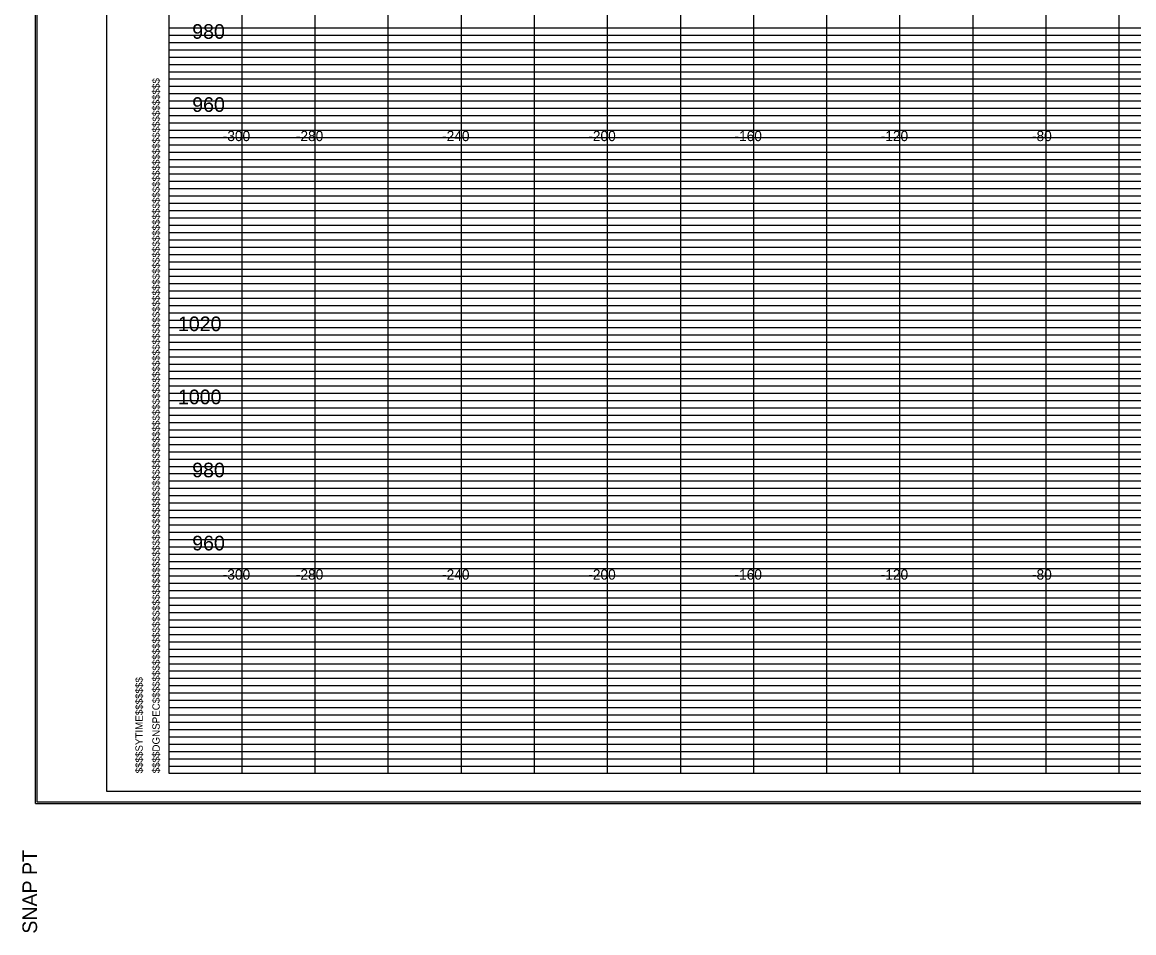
# Model space of a CAD drawing. Extents: x 2313580 to 2322968, y 282099 to 303247.
# Drawn here: x 2316841.2 to 2317145.2, y 287544 to 287793.2 of the extents above; entities that cross this region are included whole.
import ezdxf

# ---------------------------------------------------------------- set-up
doc = ezdxf.new("R2010")
doc.units = 0
for name, color, linetype in [('DESIGN - SHEET - Corner Text', 7, 'Continuous'), ('DESIGN - SHEET - Light Grid', 7, 'Continuous'), ('DESIGN - SHEET - Linework', 7, 'Continuous'), ('DESIGN - SHEET - Plot Shape', 7, 'Continuous'), ('DESIGN - TYPICAL - Text', 7, 'Continuous')]:
    doc.layers.add(name, color=color, linetype=linetype)

msp = doc.modelspace()

# ---------------------------------------------------------------- linework, layer by layer
at = {"layer": 'DESIGN - SHEET - Light Grid'}
for p, q in [((2316881.28, 287791.67), (2317041.28, 287791.67)), ((2316881.28, 287789.67), (2317041.28, 287789.67)), ((2317041.28, 287791.67), (2317201.28, 287791.67)), ((2317041.28, 287789.67), (2317201.28, 287789.67)), ((2316881.28, 287785.67), (2317041.28, 287785.67)), ((2316881.28, 287783.67), (2317041.28, 287783.67)), ((2317041.28, 287785.67), (2317201.28, 287785.67)), ((2317041.28, 287783.67), (2317201.28, 287783.67)), ((2316881.28, 287781.67), (2317041.28, 287781.67)), ((2317041.28, 287781.67), (2317201.28, 287781.67)), ((2316881.28, 287779.67), (2317041.28, 287779.67)), ((2316881.28, 287777.67), (2317041.28, 287777.67)), ((2317041.28, 287779.67), (2317201.28, 287779.67)), ((2317041.28, 287777.67), (2317201.28, 287777.67)), ((2316881.28, 287775.67), (2317041.28, 287775.67)), ((2317041.28, 287775.67), (2317201.28, 287775.67)), ((2316881.28, 287773.67), (2317041.28, 287773.67)), ((2316881.28, 287771.67), (2317041.28, 287771.67)), ((2317041.28, 287773.67), (2317201.28, 287773.67)), ((2317041.28, 287771.67), (2317201.28, 287771.67)), ((2316881.28, 287769.67), (2317041.28, 287769.67)), ((2317041.28, 287769.67), (2317201.28, 287769.67)), ((2316881.28, 287765.67), (2317041.28, 287765.67)), ((2317041.28, 287765.67), (2317201.28, 287765.67)), ((2316881.28, 287763.67), (2317041.28, 287763.67)), ((2317041.28, 287763.67), (2317201.28, 287763.67)), ((2316881.28, 287761.67), (2317041.28, 287761.67)), ((2316881.28, 287759.67), (2317041.28, 287759.67)), ((2317041.28, 287761.67), (2317201.28, 287761.67)), ((2317041.28, 287759.67), (2317201.28, 287759.67)), ((2316881.28, 287757.67), (2317041.28, 287757.67)), ((2317041.28, 287757.67), (2317201.28, 287757.67)), ((2316881.28, 287755.67), (2317041.28, 287755.67)), ((2316881.28, 287753.67), (2317041.28, 287753.67)), ((2317041.28, 287755.67), (2317201.28, 287755.67)), ((2317041.28, 287753.67), (2317201.28, 287753.67)), ((2316881.28, 287751.67), (2317041.28, 287751.67)), ((2317041.28, 287751.67), (2317201.28, 287751.67)), ((2316881.28, 287749.67), (2317041.28, 287749.67)), ((2317041.28, 287749.67), (2317201.28, 287749.67)), ((2316881.28, 287745.67), (2317041.28, 287745.67)), ((2317041.28, 287745.67), (2317201.28, 287745.67)), ((2316881.28, 287743.67), (2317041.28, 287743.67)), ((2316881.28, 287741.67), (2317041.28, 287741.67)), ((2317041.28, 287743.67), (2317201.28, 287743.67)), ((2317041.28, 287741.67), (2317201.28, 287741.67)), ((2316881.28, 287739.67), (2317041.28, 287739.67)), ((2317041.28, 287739.67), (2317201.28, 287739.67)), ((2316881.28, 287737.67), (2317041.28, 287737.67)), ((2316881.28, 287735.67), (2317041.28, 287735.67)), ((2317041.28, 287737.67), (2317201.28, 287737.67)), ((2317041.28, 287735.67), (2317201.28, 287735.67)), ((2316881.28, 287733.67), (2317041.28, 287733.67)), ((2316881.28, 287731.67), (2317041.28, 287731.67)), ((2317041.28, 287733.67), (2317201.28, 287733.67)), ((2317041.28, 287731.67), (2317201.28, 287731.67)), ((2316881.28, 287729.67), (2317041.28, 287729.67)), ((2317041.28, 287729.67), (2317201.28, 287729.67)), ((2316881.28, 287725.67), (2317041.28, 287725.67)), ((2317041.28, 287725.67), (2317201.28, 287725.67)), ((2316881.28, 287723.67), (2317041.28, 287723.67)), ((2317041.28, 287723.67), (2317201.28, 287723.67)), ((2316881.28, 287721.67), (2317041.28, 287721.67)), ((2316881.28, 287719.67), (2317041.28, 287719.67)), ((2317041.28, 287721.67), (2317201.28, 287721.67)), ((2317041.28, 287719.67), (2317201.28, 287719.67)), ((2316881.28, 287717.67), (2317041.28, 287717.67)), ((2317041.28, 287717.67), (2317201.28, 287717.67)), ((2316881.28, 287715.67), (2317041.28, 287715.67)), ((2316881.28, 287713.67), (2317041.28, 287713.67)), ((2317041.28, 287715.67), (2317201.28, 287715.67)), ((2317041.28, 287713.67), (2317201.28, 287713.67)), ((2316881.28, 287711.67), (2317041.28, 287711.67)), ((2317041.28, 287711.67), (2317201.28, 287711.67)), ((2316881.28, 287709.67), (2317041.28, 287709.67)), ((2317041.28, 287709.67), (2317201.28, 287709.67)), ((2316881.28, 287705.67), (2317041.28, 287705.67)), ((2317041.28, 287705.67), (2317201.28, 287705.67)), ((2316881.28, 287703.67), (2317041.28, 287703.67)), ((2316881.28, 287701.67), (2317041.28, 287701.67)), ((2317041.28, 287703.67), (2317201.28, 287703.67)), ((2317041.28, 287701.67), (2317201.28, 287701.67)), ((2316881.28, 287699.67), (2317041.28, 287699.67)), ((2317041.28, 287699.67), (2317201.28, 287699.67)), ((2316881.28, 287697.67), (2317041.28, 287697.67)), ((2316881.28, 287695.67), (2317041.28, 287695.67)), ((2317041.28, 287697.67), (2317201.28, 287697.67)), ((2317041.28, 287695.67), (2317201.28, 287695.67)), ((2316881.28, 287693.67), (2317041.28, 287693.67)), ((2317041.28, 287693.67), (2317201.28, 287693.67)), ((2316881.28, 287691.67), (2317041.28, 287691.67)), ((2316881.28, 287689.67), (2317041.28, 287689.67)), ((2317041.28, 287691.67), (2317201.28, 287691.67)), ((2317041.28, 287689.67), (2317201.28, 287689.67)), ((2316881.28, 287685.67), (2317041.28, 287685.67)), ((2316881.28, 287683.67), (2317041.28, 287683.67)), ((2317041.28, 287685.67), (2317201.28, 287685.67)), ((2317041.28, 287683.67), (2317201.28, 287683.67)), ((2316881.28, 287681.67), (2317041.28, 287681.67)), ((2317041.28, 287681.67), (2317201.28, 287681.67)), ((2316881.28, 287679.67), (2317041.28, 287679.67)), ((2316881.28, 287677.67), (2317041.28, 287677.67)), ((2317041.28, 287679.67), (2317201.28, 287679.67)), ((2317041.28, 287677.67), (2317201.28, 287677.67)), ((2316881.28, 287675.67), (2317041.28, 287675.67)), ((2317041.28, 287675.67), (2317201.28, 287675.67)), ((2316881.28, 287673.67), (2317041.28, 287673.67)), ((2316881.28, 287671.67), (2317041.28, 287671.67)), ((2317041.28, 287673.67), (2317201.28, 287673.67)), ((2317041.28, 287671.67), (2317201.28, 287671.67)), ((2316881.28, 287669.67), (2317041.28, 287669.67)), ((2317041.28, 287669.67), (2317201.28, 287669.67)), ((2316881.28, 287665.67), (2317041.28, 287665.67)), ((2317041.28, 287665.67), (2317201.28, 287665.67)), ((2316881.28, 287663.67), (2317041.28, 287663.67)), ((2316881.28, 287661.67), (2317041.28, 287661.67)), ((2317041.28, 287663.67), (2317201.28, 287663.67)), ((2317041.28, 287661.67), (2317201.28, 287661.67)), ((2316881.28, 287659.67), (2317041.28, 287659.67)), ((2317041.28, 287659.67), (2317201.28, 287659.67)), ((2316881.28, 287657.67), (2317041.28, 287657.67)), ((2316881.28, 287655.67), (2317041.28, 287655.67)), ((2317041.28, 287657.67), (2317201.28, 287657.67)), ((2317041.28, 287655.67), (2317201.28, 287655.67)), ((2316881.28, 287653.67), (2317041.28, 287653.67)), ((2317041.28, 287653.67), (2317201.28, 287653.67)), ((2316881.28, 287651.67), (2317041.28, 287651.67)), ((2316881.28, 287649.67), (2317041.28, 287649.67)), ((2317041.28, 287651.67), (2317201.28, 287651.67)), ((2317041.28, 287649.67), (2317201.28, 287649.67)), ((2316881.28, 287645.67), (2317041.28, 287645.67)), ((2316881.28, 287643.67), (2317041.28, 287643.67)), ((2317041.28, 287645.67), (2317201.28, 287645.67)), ((2317041.28, 287643.67), (2317201.28, 287643.67)), ((2316881.28, 287641.67), (2317041.28, 287641.67)), ((2317041.28, 287641.67), (2317201.28, 287641.67)), ((2316881.28, 287639.67), (2317041.28, 287639.67)), ((2316881.28, 287637.67), (2317041.28, 287637.67)), ((2317041.28, 287639.67), (2317201.28, 287639.67)), ((2317041.28, 287637.67), (2317201.28, 287637.67)), ((2316881.28, 287635.67), (2317041.28, 287635.67)), ((2317041.28, 287635.67), (2317201.28, 287635.67)), ((2316881.28, 287633.67), (2317041.28, 287633.67)), ((2316881.28, 287631.67), (2317041.28, 287631.67)), ((2317041.28, 287633.67), (2317201.28, 287633.67)), ((2317041.28, 287631.67), (2317201.28, 287631.67)), ((2316881.28, 287629.67), (2317041.28, 287629.67)), ((2317041.28, 287629.67), (2317201.28, 287629.67)), ((2316881.28, 287625.67), (2317041.28, 287625.67)), ((2317041.28, 287625.67), (2317201.28, 287625.67)), ((2316881.28, 287623.67), (2317041.28, 287623.67)), ((2317041.28, 287623.67), (2317201.28, 287623.67)), ((2316881.28, 287621.67), (2317041.28, 287621.67)), ((2316881.28, 287619.67), (2317041.28, 287619.67)), ((2317041.28, 287621.67), (2317201.28, 287621.67)), ((2317041.28, 287619.67), (2317201.28, 287619.67)), ((2316881.28, 287617.67), (2317041.28, 287617.67)), ((2317041.28, 287617.67), (2317201.28, 287617.67)), ((2316881.28, 287615.67), (2317041.28, 287615.67)), ((2316881.28, 287613.67), (2317041.28, 287613.67)), ((2317041.28, 287615.67), (2317201.28, 287615.67)), ((2317041.28, 287613.67), (2317201.28, 287613.67)), ((2316881.28, 287611.67), (2317041.28, 287611.67)), ((2317041.28, 287611.67), (2317201.28, 287611.67)), ((2316881.28, 287609.67), (2317041.28, 287609.67)), ((2317041.28, 287609.67), (2317201.28, 287609.67)), ((2316881.28, 287605.67), (2317041.28, 287605.67)), ((2317041.28, 287605.67), (2317201.28, 287605.67)), ((2316881.28, 287603.67), (2317041.28, 287603.67)), ((2316881.28, 287601.67), (2317041.28, 287601.67)), ((2317041.28, 287603.67), (2317201.28, 287603.67)), ((2317041.28, 287601.67), (2317201.28, 287601.67)), ((2316881.28, 287599.67), (2317041.28, 287599.67)), ((2317041.28, 287599.67), (2317201.28, 287599.67)), ((2316881.28, 287597.67), (2317041.28, 287597.67)), ((2316881.28, 287595.67), (2317041.28, 287595.67)), ((2317041.28, 287597.67), (2317201.28, 287597.67)), ((2317041.28, 287595.67), (2317201.28, 287595.67)), ((2316881.28, 287593.67), (2317041.28, 287593.67)), ((2317041.28, 287593.67), (2317201.28, 287593.67)), ((2316881.28, 287591.67), (2317041.28, 287591.67)), ((2316881.28, 287589.67), (2317041.28, 287589.67)), ((2317041.28, 287591.67), (2317201.28, 287591.67)), ((2317041.28, 287589.67), (2317201.28, 287589.67))]:
    msp.add_line(p, q, dxfattribs=at)
at = {"layer": 'DESIGN - SHEET - Linework'}
for p, q in [((2316844.82, 287579.39), (2316844.82, 288015.95)), ((2316901.28, 287587.67), (2316901.28, 288007.67)), ((2316921.28, 287587.67), (2316921.28, 288007.67)), ((2316941.28, 287587.67), (2316941.28, 288007.67)), ((2316961.28, 287587.67), (2316961.28, 288007.67)), ((2316981.28, 287587.67), (2316981.28, 288007.67)), ((2317001.28, 287587.67), (2317001.28, 288007.67)), ((2317021.28, 287587.67), (2317021.28, 288007.67)), ((2317041.28, 287587.67), (2317041.28, 288007.67)), ((2317061.28, 287587.67), (2317061.28, 288007.67)), ((2317081.28, 287587.67), (2317081.28, 288007.67)), ((2317101.28, 287587.67), (2317101.28, 288007.67)), ((2317121.28, 287587.67), (2317121.28, 288007.67)), ((2317141.28, 287587.67), (2317141.28, 288007.67)), ((2316881.28, 287787.67), (2317521.28, 287787.67)), ((2316881.28, 287767.67), (2317521.28, 287767.67)), ((2316881.28, 287747.67), (2317521.28, 287747.67)), ((2316881.28, 287727.67), (2317521.28, 287727.67)), ((2316881.28, 287707.67), (2317521.28, 287707.67)), ((2316881.28, 287687.67), (2317521.28, 287687.67)), ((2316881.28, 287667.67), (2317521.28, 287667.67)), ((2316881.28, 287647.67), (2317521.28, 287647.67)), ((2316881.28, 287627.67), (2317521.28, 287627.67)), ((2316881.28, 287607.67), (2317521.28, 287607.67)), ((2316844.82, 287579.39), (2317525.62, 287579.39))]:
    msp.add_line(p, q, dxfattribs=at)
msp.add_lwpolyline([(2316881.28, 288007.67), (2316881.28, 287587.67), (2317521.28, 287587.67), (2317521.28, 288007.67), (2316881.28, 288007.67)], dxfattribs=at)
at = {"layer": 'DESIGN - SHEET - Plot Shape'}
for points in [[(2316845.22, 288015.55), (2317525.22, 288015.55), (2317525.22, 287579.79), (2316845.22, 287579.79)], [(2316864.28, 288007.67), (2317521.28, 288007.67), (2317521.28, 287582.67), (2316864.28, 287582.67)]]:
    msp.add_lwpolyline(points, close=True, dxfattribs=at)

# ---------------------------------------------------------------- texts
at = {"layer": 'DESIGN - SHEET - Corner Text'}
for s, height, p in [('$$$$DGNSPEC$$$$$$$$$$$$$$$$$$$$$$$$$$$$$$$$$$$$$$$$$$$$$$$$$$$$$$$$$$$$$$$$$$$$$$$$$$$$$$$$$$$$$$$$$$$$$$$$$$$$$$$$$$$$$$$$$$$', 2.00004, (2316878.76, 287587.67)), ('$$$$SYTIME$$$$$$$', 2, (2316874.12, 287587.67)), ('SNAP PT  ', 4, (2316845.22, 287543.79))]:
    msp.add_text(s, height=height, rotation=90, dxfattribs=at).set_placement(p)
at = {"layer": 'DESIGN - SHEET - Linework'}
for p in [(2316901.28, 287767.67), (2316901.28, 287647.67)]:
    msp.add_text('-', height=0.0001, dxfattribs=at).set_placement(p)
at = {"layer": 'DESIGN - TYPICAL - Text'}
for s, height, p in [('980', 4, (2316887.66, 287788.67)), ('960', 4, (2316887.66, 287768.67)), ('-300', 2.8, (2316896.02, 287760.67)), ('-280', 2.8, (2316916.02, 287760.67)), ('-240', 2.8, (2316956.02, 287760.67)), ('-200', 2.8, (2316996.02, 287760.67)), ('-160', 2.8, (2317036.02, 287760.67)), ('-120', 2.8, (2317076.02, 287760.67)), ('-80', 2.8, (2317117.39, 287760.67)), ('1020', 4, (2316883.76, 287708.67)), ('1000', 4, (2316883.76, 287688.67)), ('980', 4, (2316887.66, 287668.67)), ('960', 4, (2316887.66, 287648.67)), ('-300', 2.8, (2316896.02, 287640.67)), ('-280', 2.8, (2316916.02, 287640.67)), ('-240', 2.8, (2316956.02, 287640.67)), ('-200', 2.8, (2316996.02, 287640.67)), ('-160', 2.8, (2317036.02, 287640.67)), ('-120', 2.8, (2317076.02, 287640.67)), ('-80', 2.8, (2317117.39, 287640.67))]:
    msp.add_text(s, height=height, dxfattribs=at).set_placement(p)

doc.saveas('drawing.dxf')
